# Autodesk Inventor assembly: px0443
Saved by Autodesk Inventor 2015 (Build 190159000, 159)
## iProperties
Created: 2019-05
Part Number: px0443
Checked By: TraceParts S.A.
Catalog Web Link: www.traceparts.com
Document SubType Name: Assembly
Designer: TraceParts
Company: TraceParts S.A.
Author: TraceParts
REFERENCE: PX0443
DESIGN: Plastic Electrical Connector, panel mounting, front of panel mounting, 4 poles, 5 way crimp termination, 1A, 30V
SUPPLIER: Bulgin
TraceParts.PartNumber: 90-08022019-044227
TraceParts.PartTitle: Plastic Electrical Connector, panel mounting, front of panel mounting, 4 poles, 5 way crimp termination, 1A, 30V
TraceParts.InstanceId: 90-08022019-0442272N3XX9WWY2MK673V115V3T3RA
TraceParts.PartStatus: Published
TraceParts.PartVersion: 1.0.0
TRACEPARTS: TRACEPARTS
TraceParts.PartLanguage: en
TraceParts.ClassPath: BULGIN:/F_BULGIN/BULGIN.010/BULGIN.010.010/BULGIN.010.010.020/BULGIN.010.010.020.010/BULGIN.010.010.020.010.020/90-08022019-044227
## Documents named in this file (6)
- C:\TPO v2\SharedFS\Outgoing\px0443.iam
- C:\TPO v2\SharedFS\Outgoing\px0443_01.ipt
- C:\TPO v2\SharedFS\Outgoing\px0443_02.ipt
- C:\TPO v2\SharedFS\Outgoing\px0443_03.ipt
- C:\TPO v2\SharedFS\Outgoing\px0443_04.ipt
- C:\TPO v2\SharedFS\Outgoing\px0443_05.ipt
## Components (5 placed, 5 different names)
1. px0443_01:1
2. px0443_02:1
3. px0443_03:1
4. px0443_04:1
5. px0443_05:1
